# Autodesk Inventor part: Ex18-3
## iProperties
Author: Elise Moss
Revision Number: A
Created: 2001-09
Part Number: Ex18-3
Document SubType Name: Modeling
Designer: Elise Moss
Description: SCREW
Control State: 0
Master: False
Checked Out: False
PropertySet Name: Design Tracking Control
Length Units: 11272
Angle Units: 11279
Time Units: 11290
Mass Units: 11286
Shininess: 3
Angle Display Precision: 2
Document Length Units: 11272
Document Angle Units: 11286
Document Time Units: 11279
Document Mass Units: 11290
Document Length Units Precision: 3
Document Angle Units Precision: 0
Compacted: False
PropertySet Name: _Private Model Information
Density: 0.0
Volumn: 0.0
Area: 0.0
PropertySet Name: Model Information
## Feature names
1. Extrusion1
2. Extrusion2
3. Extrusion3
4. Extrusion4
5. knurl [Extrusion]
6. Extrusion6
7. Chamfer1
8. Chamfer2
9. Hole1
